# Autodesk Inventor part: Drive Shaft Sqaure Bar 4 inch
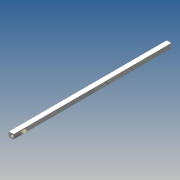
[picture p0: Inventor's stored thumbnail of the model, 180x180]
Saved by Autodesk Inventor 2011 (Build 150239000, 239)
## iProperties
Company: Autodesk Inc.
Created: 2010-06
Document SubType Name: Modeling
Designer: Autodesk Inc.
Density: 1 g/cm^3
Catalog Web Link: http://vexrobotics.com/products
Vendor: Innovation First, Inc.
Part Number: Drive Shaft Sqaure Bar 4 inch
Author: Autodesk Inc.
Title: VEX Robotics Kit of Parts
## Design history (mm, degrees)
sketch "Sketch1"
  geometry: L1 (0.378, 1.587)-(-0.378, 1.587); L2 (-1.334, 1.587)-(-0.378, 1.587); L3 (-1.588, 0.378)-(-1.588, -0.378); L4 (-0.378, -1.588)-(0.378, -1.588); L5 (-1.587, -1.334)-(-1.588, -0.378); L6 (-0.378, -1.588)-(-1.334, -1.587); L7 (-1.588, 0.378)-(-1.587, 1.334); L8 (1.587, 1.334)-(1.588, 0.378); L9 (0.378, 1.587)-(1.334, 1.587); L10 (1.588, -0.378)-(1.588, 0.378); L11 (1.334, -1.587)-(0.378, -1.588); L12 (1.588, -0.378)-(1.587, -1.334); A1 r 1.632 centre (0, 0) between (-0.378, 1.587) and (-1.588, 0.378); A2 r 1.632 centre (0, 0) between (-0.378, 1.587) and (-1.588, 0.378); A3 r 1.632 centre (0, 0) between (-1.588, -0.378) and (-0.378, -1.588); A4 r 1.632 centre (0, 0) between (-1.588, -0.378) and (-0.378, -1.588); A5 r 1.632 centre (0, 0) between (1.588, 0.378) and (0.378, 1.587); A6 r 1.632 centre (0, 0) between (1.588, 0.378) and (0.378, 1.587); A7 r 1.632 centre (0, 0) between (0.378, -1.588) and (1.588, -0.378); A8 r 1.632 centre (0, 0) between (0.378, -1.588) and (1.588, -0.378); 1 further point
  constraints: 24 end point, 16 point on circle, 8 centre point, 8 other
extrude "Extrusion1" new body sketch "Sketch1" distance "d0" = 101.6; taper "d1" = 0 deg
workplane "Work Plane1"
  workaxis "Work Axis1"
sketch "Sketch2"
  geometry: L1 (0, 0)-(0.352, 0); L2 (0.352, 0)-(0.352, 2.14); L3 (0.352, 2.14)-(-0.254, 2.14); L4 (0, 0)-(0, 1.39); L5 (-121.99, 0)-(20.742, 0) reference; A1 r 0.772 centre (-0.757, 1.554) between (-0.179, 2.065) and (-0.254, 2.14); 1 further point
  constraints: 8 end point, 2 perpendicular, 2 point on circle, 1 centre point, 3 other
revolve "Revolution1" sketch "Sketch2" stored, may be unused: angle "d3" = 90 deg
workplane "Work Plane2"
mirror "Mirror1"
body "Solid1"
other parameters: "d2" = 90 deg
